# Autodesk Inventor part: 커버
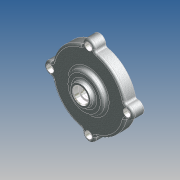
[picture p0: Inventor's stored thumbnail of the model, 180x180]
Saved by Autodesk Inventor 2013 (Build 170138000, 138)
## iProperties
Company: 한국ATC센터
Created: 2014-07
Part Number: 커버
Document SubType Name: 모델링
Designer: KYOUNG IL JANG
Material: 일반
Mass: 72.5678 g
Surface Area: 278.607 cm^2
Volume: 72.5678 cm^3
Density: 1 g/cm^3
변환 표준: STEP AP214IS
파일 이름: C:\Users\SeoGD\Desktop\?쒗뿕\而ㅻ쾭-1.stp
전처리기: Build: 253, Release: 2010 SP1 - Date: Wed 07/29/2009
전송 단위: 밀리미터
불확실성: 0.01
Author: KYOUNG IL JANG
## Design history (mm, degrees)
sketch "스케치1"
  geometry: L1 (0, 0)-(0, 26); L2 (50, 0)-(50, 15); L3 (50, 15)-(25, 15); L4 (25, 15)-(25, 21); L5 (25, 21)-(15, 21); L6 (15, 21)-(13.66, 26); L7 (13.66, 26)-(10, 26); L8 (50, 0)-(45, 0); L9 (45, 0)-(45, 10); L10 (45, 10)-(14.5, 10); L11 (14.5, 10)-(13.266, 3); L12 (13.266, 3)-(11, 3); L13 (11, 3)-(11, 16); L14 (11, 16)-(7.5, 16); L15 (7.5, 16)-(7.5, 19); L16 (7.5, 19)-(10, 19); L17 (10, 19)-(10, 26)
  constraints: 34 end point, 10 parallel, 2 perpendicular, 2 point on line, 1 vertical
  dimensions: "d11" = 100 diameter of L2 L1; "d12" = 22 diameter of L13 L1; "d13" = 90 diameter of L9 L1; "d14" = 15 distance between parallel lines of L3 L8; "d15" = 10 distance between parallel lines of L8 L10; "d16" = 29 diameter of L10.end L1; "d17" = 100 deg angle of L11 L10; "d18" = 7 distance between parallel lines of L12 L10; "d19" = 13 distance between parallel lines of L14 L12; "d20" = 3 distance between parallel lines of L16 L14; "d21" = 15 diameter of L15 L1; "d22" = 20 diameter of L17 L1; "d23" = 30 diameter of L5.end L1; "d24" = 6 distance between parallel lines of L5 L3; "d25" = 50 diameter of L4 L1; "d26" = 105 deg angle of L5 L6; "d50" = 26 distance of L1.start L1.end
revolve "회전1" sketch "스케치1" stored, may be unused: angle "d27" = 90 deg
sketch "스케치2" dims "d29" = 104
  geometry: A1 r 8.5 centre (0, 52) between (8.074, 49.344) and (-8.074, 49.344); A2 r 50 centre (0, 0) between (-8.074, 49.344) and (8.074, 49.344) reference; 2 further points
  constraints: 4 point on circle, 2 vertical alignment, 1 centre point, 1 coincident, 2 other
  dimensions: "d28" = 17 diameter of A1
extrude "돌출1" join sketch "스케치2" stored distance "d30" = 10; taper "d31" = 0 deg
fillet "모깎기3" dims "d32" = 3
fillet "모깎기4" dims "d45" = 3, "d46" = 0.2
chamfer "모따기1" distance "d47" = 1; stored, may be unused: second distance "d48" = 2, angle "d49" = 45 deg
hole "구멍2" diameter "d38" = 5.5; stored, may be unused: countersink angle "d42" = 90 deg, drill point angle "d44" = 118 deg; dims "d36" = 10, "d37" = 10, "d39" = 6, "d40" = 9.5, "d41" = 5.4, "d43" = 8
node "솔리드1"
node "솔리드 본체"
node "곡면 본체"
pattern_circular "원형 패턴1" dims angle "d34" = 360 deg
pattern_circular "원형 패턴2" dims angle "d52" = 360 deg
node "솔리드2"
